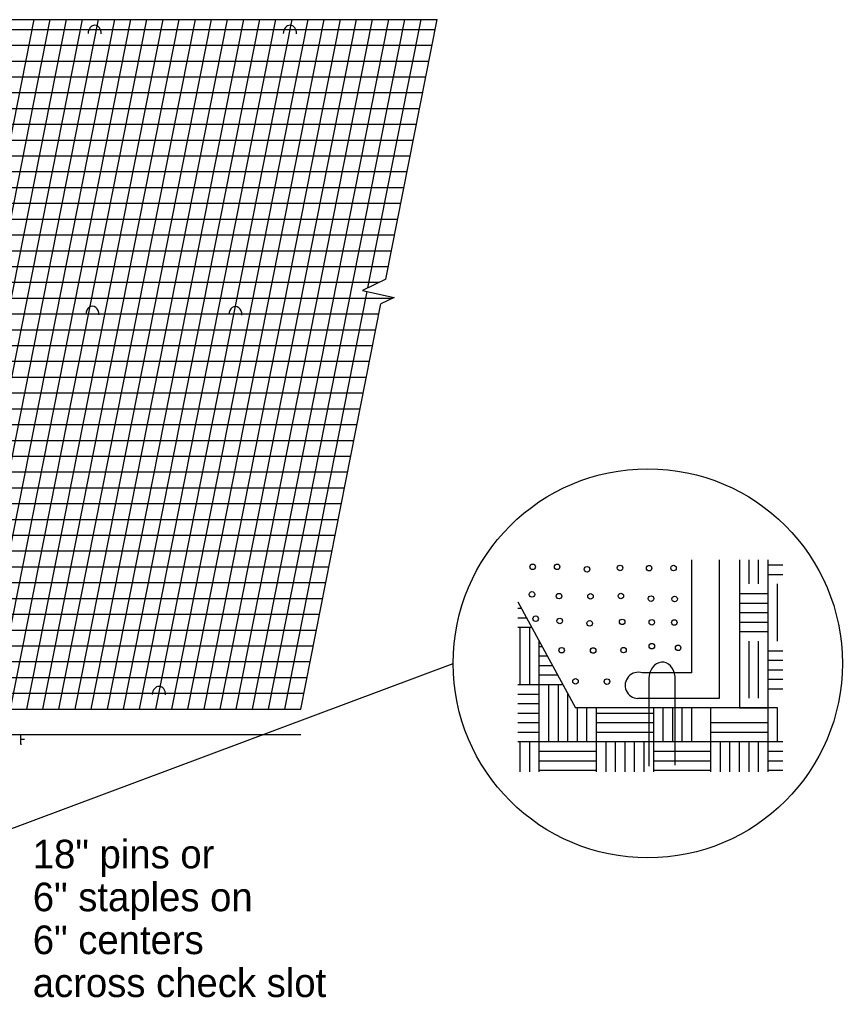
# Model space of a CAD drawing. Extents: x 1083.1 to 1117.1, y 719.4 to 741.4.
# Drawn here: x 1108.815 to 1112.842, y 733.669 to 738.456 of the extents above; entities that cross this region are included whole.
import ezdxf

# ---------------------------------------------------------------- set-up
doc = ezdxf.new("R2010")
doc.units = 0
doc.layers.add('ST_Details', color=7, linetype='Continuous')
doc.layers.add('ST_Text', color=7, linetype='Continuous')

msp = doc.modelspace()

# ---------------------------------------------------------------- linework, layer by layer
at = {"layer": 'ST_Details'}
for p, q in [((1108.2194, 735.0804), (1108.8865, 738.4558)), ((1108.2494, 738.4558), (1110.8584, 738.4558)), ((1108.2982, 735.0804), (1108.9654, 738.4558)), ((1108.3771, 735.0804), (1109.0442, 738.4558)), ((1108.456, 735.0804), (1109.1231, 738.4558)), ((1108.5349, 735.0804), (1109.202, 738.4558)), ((1108.6138, 735.0804), (1109.2809, 738.4558)), ((1108.6926, 735.0804), (1109.3597, 738.4558)), ((1108.7715, 735.0804), (1109.4386, 738.4558)), ((1108.8504, 735.0804), (1109.5175, 738.4558)), ((1108.9293, 735.0804), (1109.5964, 738.4558)), ((1109.0081, 735.0804), (1109.6753, 738.4558)), ((1109.087, 735.0804), (1109.7541, 738.4558)), ((1109.1659, 735.0804), (1109.833, 738.4558)), ((1109.2448, 735.0804), (1109.9119, 738.4558)), ((1109.3237, 735.0804), (1109.9908, 738.4558)), ((1109.4025, 735.0804), (1110.0696, 738.4558)), ((1109.4815, 735.0804), (1110.1485, 738.4558)), ((1109.5603, 735.0804), (1110.2274, 738.4558)), ((1109.6392, 735.0804), (1110.3062, 738.4558)), ((1109.718, 735.0804), (1110.3851, 738.4558)), ((1109.797, 735.0804), (1110.464, 738.4558)), ((1109.8758, 735.0804), (1110.5429, 738.4558)), ((1109.9547, 735.0804), (1110.6217, 738.4558)), ((1110.0336, 735.0804), (1110.7006, 738.4558)), ((1110.52, 737.1425), (1110.7795, 738.4558)), ((1110.6071, 737.1847), (1110.8584, 738.4558)), ((1108.2399, 738.4076), (1110.8489, 738.4076)), ((1108.2245, 738.3302), (1110.8335, 738.3302)), ((1108.2093, 738.2529), (1110.8183, 738.2529)), ((1108.194, 738.1755), (1110.803, 738.1755)), ((1108.1786, 738.0981), (1110.7877, 738.0981)), ((1108.1634, 738.0208), (1110.7724, 738.0208)), ((1108.148, 737.9434), (1110.757, 737.9434)), ((1108.1328, 737.866), (1110.7419, 737.866)), ((1108.1175, 737.7886), (1110.7265, 737.7886)), ((1108.1021, 737.7113), (1110.7113, 737.7113)), ((1108.087, 737.6339), (1110.696, 737.6339)), ((1108.0716, 737.5565), (1110.6807, 737.5565)), ((1108.0564, 737.4791), (1110.6654, 737.4791)), ((1108.041, 737.4018), (1110.65, 737.4018)), ((1108.0258, 737.3244), (1110.6348, 737.3244)), ((1108.0105, 737.247), (1110.6195, 737.247)), ((1107.9951, 737.1696), (1110.576, 737.1696)), ((1110.6071, 737.1847), (1110.4934, 737.1297)), ((1110.1125, 735.0804), (1110.5165, 737.1247)), ((1110.4934, 737.1297), (1110.648, 737.0959)), ((1107.9799, 737.0923), (1110.6404, 737.0923)), ((1110.1914, 735.0804), (1110.5834, 737.0646)), ((1110.648, 737.0959), (1110.5834, 737.0646)), ((1107.9645, 737.0149), (1110.5736, 737.0149)), ((1107.9493, 736.9375), (1110.5584, 736.9375)), ((1107.934, 736.8602), (1110.543, 736.8602)), ((1107.9186, 736.7828), (1110.5278, 736.7828)), ((1107.9035, 736.7054), (1110.5125, 736.7054)), ((1107.8881, 736.628), (1110.4972, 736.628)), ((1107.8729, 736.5507), (1110.4819, 736.5507)), ((1107.8575, 736.4733), (1110.4666, 736.4733)), ((1107.8422, 736.3959), (1110.4513, 736.3959)), ((1107.827, 736.3185), (1110.436, 736.3185)), ((1107.8116, 736.2412), (1110.4207, 736.2412)), ((1107.7964, 736.1638), (1110.4054, 736.1638)), ((1107.781, 736.0864), (1110.3902, 736.0864)), ((1107.7657, 736.0091), (1110.3749, 736.0091)), ((1107.7505, 735.9317), (1110.3596, 735.9317)), ((1107.7352, 735.8544), (1110.3443, 735.8544)), ((1107.72, 735.7769), (1110.329, 735.7769)), ((1112.1036, 735.8115), (1112.1036, 735.2577)), ((1112.2379, 735.8115), (1112.2379, 735.1325)), ((1112.3379, 735.8115), (1112.3379, 735.0867)), ((1112.3846, 735.693), (1112.3846, 735.8115)), ((1112.4312, 735.693), (1112.4312, 735.8115)), ((1112.4779, 735.0867), (1112.4779, 735.8115)), ((1112.4779, 735.7863), (1112.5507, 735.7863)), ((1112.4779, 735.7397), (1112.5507, 735.7397)), ((1107.7046, 735.6996), (1110.3137, 735.6996)), ((1112.5246, 735.4132), (1112.5246, 735.693)), ((1112.3379, 735.6463), (1112.4779, 735.6463)), ((1107.6894, 735.6222), (1110.2984, 735.6222)), ((1111.2537, 735.6063), (1111.5359, 735.0867)), ((1112.3379, 735.5998), (1112.4779, 735.5998)), ((1107.674, 735.5449), (1110.2831, 735.5449)), ((1111.2537, 735.5742), (1111.2712, 735.5742)), ((1112.3379, 735.5532), (1112.4779, 735.5532)), ((1111.2537, 735.5275), (1111.2966, 735.5275)), ((1112.3379, 735.5065), (1112.4779, 735.5065)), ((1107.6587, 735.4674), (1110.2678, 735.4674)), ((1111.2537, 735.4808), (1111.3219, 735.4808)), ((1111.2651, 735.341), (1111.2651, 735.4808)), ((1111.3117, 735.341), (1111.3117, 735.4808)), ((1112.3379, 735.4598), (1112.4779, 735.4598)), ((1107.6435, 735.3901), (1110.2525, 735.3901)), ((1111.3584, 734.7735), (1111.3584, 735.4135)), ((1112.3846, 735.2733), (1112.3846, 735.4132)), ((1112.4312, 735.2733), (1112.4312, 735.4132)), ((1111.2651, 735.201), (1111.2651, 735.341)), ((1111.3117, 735.201), (1111.3117, 735.341)), ((1111.3584, 735.3875), (1111.3726, 735.3875)), ((1111.3584, 735.341), (1111.3979, 735.341)), ((1112.4779, 735.3665), (1112.5507, 735.3665)), ((1107.6281, 735.3127), (1110.2372, 735.3127)), ((1107.8364, 734.1434), (1110.9368, 735.3045)), ((1111.3584, 735.2943), (1111.4232, 735.2943)), ((1112.4779, 735.3198), (1112.5507, 735.3198)), ((1111.3584, 735.2477), (1111.4486, 735.2477)), ((1112.1036, 735.2577), (1111.8619, 735.2577)), ((1112.3846, 735.1333), (1112.3846, 735.2733)), ((1112.4312, 735.1333), (1112.4312, 735.2733)), ((1112.4779, 735.2733), (1112.5507, 735.2733)), ((1107.6129, 735.2354), (1110.222, 735.2354)), ((1111.2537, 735.201), (1111.4739, 735.201)), ((1111.4051, 734.9212), (1111.4051, 735.201)), ((1111.4517, 734.9212), (1111.4517, 735.201)), ((1111.8944, 735.2298), (1111.8944, 734.8013)), ((1112.0231, 734.8063), (1112.0231, 735.2397)), ((1112.4779, 735.2267), (1112.5507, 735.2267)), ((1107.5975, 735.1579), (1110.2067, 735.1579)), ((1111.2537, 735.1543), (1111.3584, 735.1543)), ((1111.4984, 734.9212), (1111.4984, 735.1558)), ((1112.4779, 735.18), (1112.5507, 735.18)), ((1111.2537, 735.1077), (1111.3584, 735.1077)), ((1112.2379, 735.1325), (1111.8406, 735.1325)), ((1107.5822, 735.0804), (1110.1914, 735.0804)), ((1111.2537, 735.0612), (1111.3584, 735.0612)), ((1112.2524, 735.0867), (1111.5359, 735.0867)), ((1111.5451, 734.9212), (1111.5451, 735.0867)), ((1111.5917, 734.9212), (1111.5917, 735.0867)), ((1111.6382, 734.7735), (1111.6382, 735.0867)), ((1111.6382, 735.0612), (1111.7782, 735.0612)), ((1111.7782, 735.0612), (1111.9182, 735.0612)), ((1111.9182, 734.7735), (1111.9182, 735.0867)), ((1111.9647, 734.9212), (1111.9647, 735.0867)), ((1112.0114, 734.9212), (1112.0114, 735.0867)), ((1112.0581, 734.9212), (1112.0581, 735.0867)), ((1112.1047, 734.9212), (1112.1047, 735.0867)), ((1112.1981, 734.7735), (1112.1981, 735.0867)), ((1112.1981, 735.0807), (1112.1981, 735.0867)), ((1112.5246, 735.0867), (1112.2524, 735.0867)), ((1112.3379, 735.0867), (1112.4779, 735.0867)), ((1112.4779, 734.7735), (1112.4779, 735.0867)), ((1112.5246, 734.9212), (1112.5246, 735.0867)), ((1111.2537, 735.0145), (1111.3584, 735.0145)), ((1111.6382, 735.0145), (1111.7782, 735.0145)), ((1111.7782, 735.0145), (1111.9182, 735.0145)), ((1112.1972, 735.0145), (1112.4779, 735.0145)), ((1111.2537, 734.9678), (1111.3584, 734.9678)), ((1111.6382, 734.9678), (1111.7782, 734.9678)), ((1111.7782, 734.9678), (1111.9182, 734.9678)), ((1112.2009, 734.9678), (1112.4779, 734.9678)), ((1107.6322, 734.9563), (1110.1914, 734.9563)), ((1108.8217, 734.9064), (1108.8217, 734.9563)), ((1108.8217, 734.9563), (1108.8542, 734.9563)), ((1108.8217, 734.9329), (1108.839, 734.9329)), ((1108.8217, 734.9096), (1108.8239, 734.9096)), ((1111.2537, 734.9212), (1112.2524, 734.9212)), ((1111.2651, 734.7813), (1111.2651, 734.9212)), ((1111.3117, 734.7813), (1111.3117, 734.9212)), ((1111.6849, 734.7813), (1111.6849, 734.9212)), ((1111.7316, 734.7813), (1111.7316, 734.9212)), ((1111.7782, 734.7813), (1111.7782, 734.9212)), ((1111.8249, 734.7813), (1111.8249, 734.9212)), ((1111.8716, 734.7813), (1111.8716, 734.9212)), ((1112.2447, 734.7813), (1112.2447, 734.9212)), ((1112.2524, 734.9212), (1112.5507, 734.9212)), ((1112.2914, 734.7813), (1112.2914, 734.9212)), ((1112.3379, 734.7813), (1112.3379, 734.9212)), ((1112.3846, 734.7813), (1112.3846, 734.9212)), ((1112.4312, 734.7813), (1112.4312, 734.9212)), ((1111.3584, 734.8745), (1111.6382, 734.8745)), ((1111.9182, 734.8745), (1112.1981, 734.8745)), ((1112.4779, 734.8745), (1112.5507, 734.8745)), ((1111.3584, 734.8278), (1111.6382, 734.8278)), ((1111.9182, 734.8278), (1112.1981, 734.8278)), ((1112.4779, 734.8278), (1112.5507, 734.8278)), ((1111.2651, 734.7735), (1111.2651, 734.7813)), ((1111.3117, 734.7735), (1111.3117, 734.7813)), ((1111.3584, 734.7813), (1111.6382, 734.7813)), ((1111.6849, 734.7735), (1111.6849, 734.7813)), ((1111.7316, 734.7735), (1111.7316, 734.7813)), ((1111.7782, 734.7735), (1111.7782, 734.7813)), ((1111.8249, 734.7735), (1111.8249, 734.7813)), ((1111.8716, 734.7735), (1111.8716, 734.7813)), ((1111.9182, 734.7813), (1112.1981, 734.7813)), ((1112.2447, 734.7735), (1112.2447, 734.7813)), ((1112.2914, 734.7735), (1112.2914, 734.7813)), ((1112.3379, 734.7735), (1112.3379, 734.7813)), ((1112.3846, 734.7735), (1112.3846, 734.7813)), ((1112.4312, 734.7735), (1112.4312, 734.7813)), ((1112.4779, 734.7813), (1112.5507, 734.7813))]:
    msp.add_line(p, q, dxfattribs=at)
msp.add_circle((1111.8892, 735.3045), 0.9524, dxfattribs=at)
msp.add_arc((1111.8424, 735.1966), 0.0641, 72.3221, 268.3456, dxfattribs=at)
for centre, major_axis, start_param, end_param in [((1109.1829, 738.3871), (0.001, 0.041), 4.7124, 7.853992), ((1110.1381, 738.3871), (0.001, 0.041), 4.7124, 7.853992), ((1109.1713, 737.012), (0.0011, 0.041), 4.7124, 7.853993), ((1109.8709, 737.0104), (0.0011, 0.041), 4.7124, 7.853993), ((1111.959, 735.2283), (0.002, 0.0819), 4.878529, 7.853992), ((1109.4971, 735.1508), (0.001, 0.041), 4.7124, 7.853992)]:
    msp.add_ellipse(centre, major_axis=major_axis, ratio=0.78812, start_param=start_param, end_param=end_param, dxfattribs=at)
for centre in [(1111.3258, 735.7767), (1111.4454, 735.777), (1111.592, 735.765), (1111.7536, 735.7715), (1111.8957, 735.7705), (1112.0153, 735.7708), (1111.3226, 735.6419), (1111.455, 735.6336), (1111.609, 735.6323), (1111.7576, 735.6343), (1111.9052, 735.6213), (1112.0204, 735.6196), (1111.3406, 735.5227), (1111.4584, 735.512), (1111.605, 735.5), (1111.7637, 735.5073), (1111.9087, 735.5055), (1112.0193, 735.5042), (1111.9088, 735.3887), (1112.0375, 735.3802), (1111.468, 735.3686), (1111.622, 735.3672), (1111.7706, 735.3692), (1111.5354, 735.2166), (1111.6893, 735.2152)]:
    msp.add_ellipse(centre, major_axis=(0.0135, 0), ratio=0.999895, dxfattribs=at)

# ---------------------------------------------------------------- texts
at = {"layer": 'ST_Text'}
for s, p in [('18" pins or', (1108.8798, 734.301)), ('6" staples on', (1108.8798, 734.091)), ('6" centers', (1108.8798, 733.881)), ('across check slot', (1108.8798, 733.671))]:
    msp.add_text(s, height=0.14, dxfattribs=at).set_placement(p)

doc.saveas('drawing.dxf')
